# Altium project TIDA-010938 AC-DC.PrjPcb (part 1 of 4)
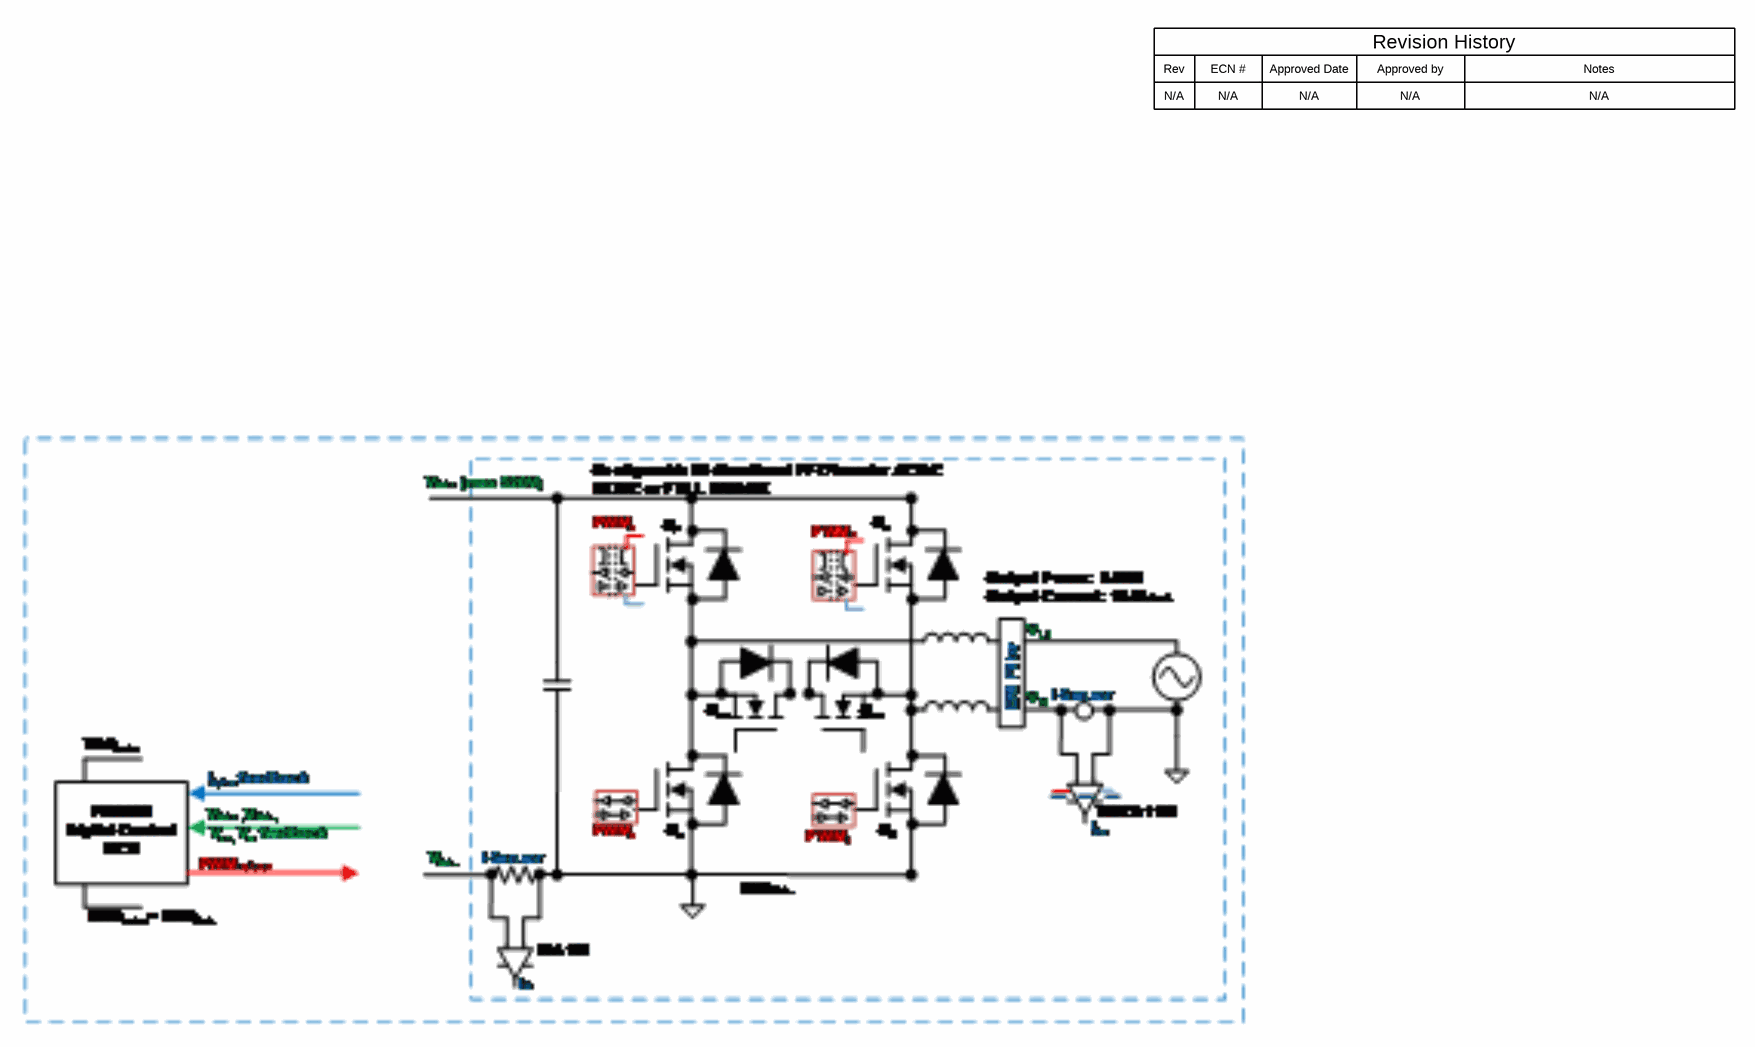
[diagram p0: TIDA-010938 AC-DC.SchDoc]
CopyrightYear: 2023; PCB_Layout: Vedatroyee Ghosh; PCB_Rev: E1; PRJ_Customer: Public Release; PRJ_Engineer: Vedatroyee Ghosh; PRJ_Number: TIDA-010938 AC-DC; PRJ_Title: TIDA-010938 AC-DC; SCH_Rev: E1; TechSupport: http://www.ti.com/support; TID: A0498176
11 sheets, 712 parts. Net scope: flat (ports and power ports of the same name join across sheets).
Board file: TIDA-010938 AC-DC.PcbDoc
Sheets:
  TIDA-010938 AC-DC.SchDoc
    Designator = TIDA-010938 AC-DC_Cover Sheet.SchDoc
      Designator = TIDA-010938 AC-DC_Power Stage_BranchA.SchDoc
      Designator = TIDA-010938 AC-DC_Power Stage_BranchB.SchDoc
      Designator = TIDA-010938 AC-DC_EMI Protection Stage.SchDoc
      Designator = TIDA-010938 AC-DC_Voltage Measurement.SchDoc
      Designator = TIDA-010938 AC-DC_Control Stage.SchDoc
        Designator = TIDA-010938 AC-DC_Communication.SchDoc
        Designator = TIDA-010938 AC-DC_OpAmp.SchDoc
      Designator = TIDA-010938 AC-DC_Hardware.SchDoc
      Designator = TIDA-010938 AC-DC_Aux Power Supply.SchDoc

## Sheet TIDA-010938 AC-DC.SchDoc
size 431 x 279 mm; Date: Not shown in title block; ApprovedBy: Not shown in title block; CheckedBy: Not shown in title block; Author: Not shown in title block; CompanyName: Not shown in title block; Engineer: Not shown in title block; Organization: Not shown in title block; Address1: Not shown in title block; Address2: Not shown in title block; Address3: Not shown in title block; Address4: Not shown in title block; DocumentNumber: 1; Revision: Use project parameter SCH_Rev; SheetNumber: 1; SheetTotal: 11; PageSetup: Record=PageOptions¦CenterHorizontal=True¦CenterVertical=True¦PrintScale=1.00¦XCorrection=1.00¦YCorrection=1.00¦PrintKind=0¦BorderSize=5000000¦LeftOffset=0¦BottomOffset=0¦Orientation=2¦PaperLength=1000¦PaperWidth=1000¦Scale=100¦PaperSource=15¦PrintQuality=600¦MediaType=1¦DitherType=10¦PaperKind=Letter¦PrintScaleMode=1

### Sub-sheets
Designator = TIDA-010938 AC-DC_Cover Sheet: no entries

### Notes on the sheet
- Rev
- N/A
- ECN #
- Approved Date
- Approved by
- Revision History
- Notes

## Sheet TIDA-010938 AC-DC_Cover Sheet.SchDoc
size 431 x 279 mm; Date: Not shown in title block; ApprovedBy: Not shown in title block; CheckedBy: Not shown in title block; Author: Not shown in title block; CompanyName: Not shown in title block; Engineer: Not shown in title block; Organization: Not shown in title block; Address1: Not shown in title block; Address2: Not shown in title block; Address3: Not shown in title block; Address4: Not shown in title block; DocumentNumber: 8; Revision: Use project parameter SCH_Rev; SheetNumber: 2; SheetTotal: 11; PageSetup: Record=PageOptions¦CenterHorizontal=True¦CenterVertical=True¦PrintScale=1.00¦XCorrection=1.00¦YCorrection=1.00¦PrintKind=0¦BorderSize=5000000¦LeftOffset=0¦BottomOffset=0¦Orientation=2¦PaperLength=1000¦PaperWidth=1000¦Scale=100¦PaperSource=15¦PrintQuality=600¦MediaType=1¦DitherType=10¦PaperKind=Letter¦PrintScaleMode=1
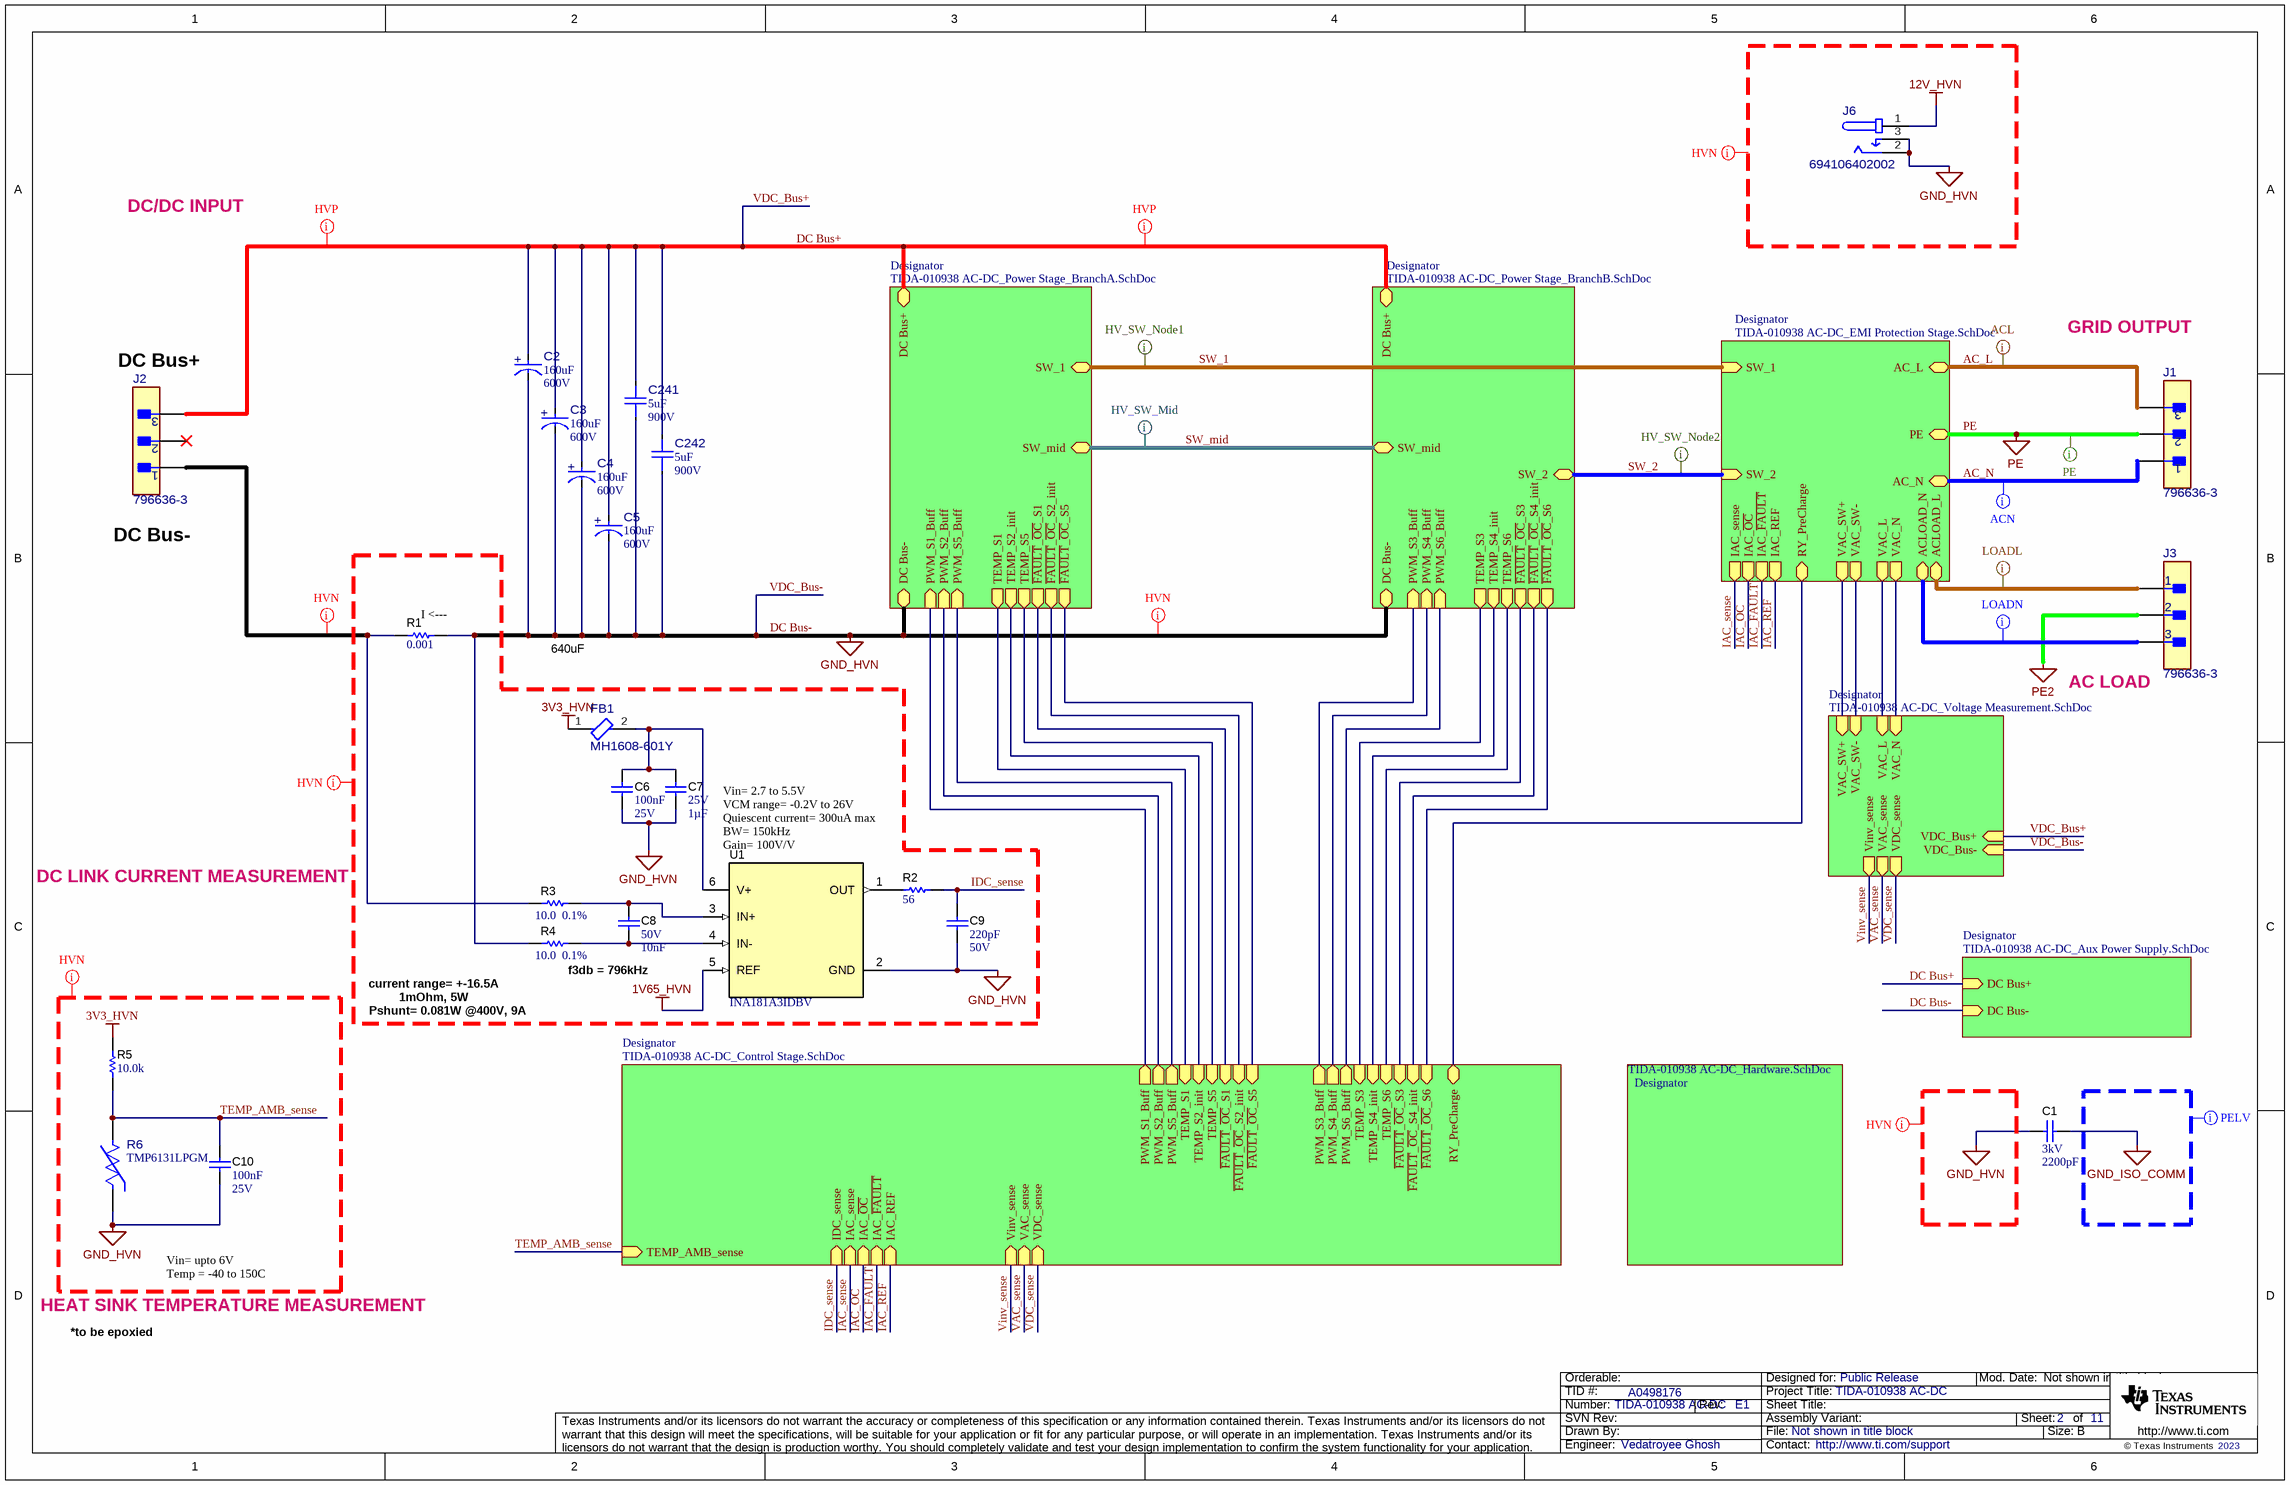
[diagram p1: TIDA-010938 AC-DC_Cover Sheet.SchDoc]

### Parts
C1  VDC_V: 3kV  ValueDisplayed: 2200pF  [CK45_1250x600x1650]  (hidden comment: CK45-B3FD222KYVNA)
C2  ValueDisplayed: 160uF  VDC_V: 600V  [FP-ALH82D161DD600_RADIAL-MFG]  (hidden comment: ALH82D161DD600)
C3  ValueDisplayed: 160uF  VDC_V: 600V  [FP-ALH82D161DD600_RADIAL-MFG]  (hidden comment: ALH82D161DD600)
C4  ValueDisplayed: 160uF  VDC_V: 600V  [FP-ALH82D161DD600_RADIAL-MFG]  (hidden comment: ALH82D161DD600)
C5  ValueDisplayed: 160uF  VDC_V: 600V  [FP-ALH82D161DD600_RADIAL-MFG]  (hidden comment: ALH82D161DD600)
C6  Cap_F: 100nF  VDC_V: 25V  [0603]  (hidden comment: 06033C104JAT2A)
C7  VDC_V: 25V  ValueDisplayed: 1µF  [0603]  (hidden comment: TMK107BJ105KA-T)
C8  VDC_V: 50V  Cap_F: 10nF  [0603]  (hidden comment: 885012206089)
C9  Cap_F: 220pF  VDC_V: 50V  [0603]  (hidden comment: GRM188R71H221KA01D)
C10  Cap_F: 100nF  VDC_V: 25V  [0603]  (hidden comment: 06033C104JAT2A)
C241  ValueDisplayed: 5uF  VDC_V: 900V  [FP-C4AKOBU4500A31J_RADIAL-MFG]  (hidden comment: C4AKOBU4500A31J)
C242  ValueDisplayed: 5uF  VDC_V: 900V  [FP-C4AKOBU4500A31J_RADIAL-MFG]  (hidden comment: C4AKOBU4500A31J)
FB1  MH1608-601Y  [FP-MH1608-601Y_0603-MFG]
J1  796636-3  [FP-796636-3_HDR3-MFG]
J2  796636-3  [FP-796636-3_HDR3-MFG]
J3  796636-3  [FP-796636-3_HDR3-MFG]
J6  694106402002  [FP-694106402002_CONN_PWR_10MM7_9MM0-MFG]
R1  ValueDisplayed: 0.001  [CSS2H-2512_H077Y042]  (hidden comment: CSS2H-2512R-1L00F)
R2  ValueDisplayed: 56  [0603]  (hidden comment: RG1608P-560-B-T5)
R3  Tolerance_%: 0.1%  ValueDisplayed: 10.0  [0603]  (hidden comment: RT0603BRD0710RL)
R4  Tolerance_%: 0.1%  ValueDisplayed: 10.0  [0603]  (hidden comment: RT0603BRD0710RL)
R5  ValueDisplayed: 10.0k  [0603]  (hidden comment: RG1608P-103-B-T5)
R6  TMP6131LPGM  [LPG0002A-MFG]
U1  INA181A3IDBV  [DBV0006A_N]

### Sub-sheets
Designator = TIDA-010938 AC-DC_Power Stage_BranchA.SchDoc: TEMP_S5 (out), TEMP_S1 (out), DC Bus+ (bidir), SW_mid (bidir), SW_1 (bidir), DC Bus- (bidir), PWM_S1_Buff (in), PWM_S5_Buff (in), PWM_S2_Buff (in), TEMP_S2_init (out), ~{FAULT}_~{OC}_S5 (out), ~{FAULT}_~{OC}_S1 (out), ~{FAULT}_~{OC}_S2_init (out)
Designator = TIDA-010938 AC-DC_Power Stage_BranchB.SchDoc: TEMP_S6 (out), TEMP_S3 (out), DC Bus+ (bidir), SW_mid (bidir), SW_2 (bidir), DC Bus- (bidir), PWM_S6_Buff (in), PWM_S3_Buff (in), PWM_S4_Buff (in), TEMP_S4_init (out), ~{FAULT}_~{OC}_S6 (out), ~{FAULT}_~{OC}_S3 (out), ~{FAULT}_~{OC}_S4_init (out)
Designator = TIDA-010938 AC-DC_EMI Protection Stage.SchDoc: AC_L (bidir), AC_N (bidir), SW_1 (in), SW_2 (in), VAC_SW+ (out), VAC_SW- (out), VAC_L (out), VAC_N (out), IAC_sense (out), IAC_~{OC} (out), IAC_~{FAULT} (out), IAC_REF (out), RY_PreCharge (bidir), PE (bidir), ACLOAD_L (bidir), ACLOAD_N (bidir)
Designator = TIDA-010938 AC-DC_Voltage Measurement.SchDoc: VDC_sense (out), Vinv_sense (out), VAC_N (in), VAC_L (in), VAC_SW- (in), VAC_SW+ (in), VAC_sense (out), VDC_Bus+ (in), VDC_Bus- (in)
Designator = TIDA-010938 AC-DC_Control Stage.SchDoc: IAC_REF (in), IAC_sense (in), VAC_sense (in), Vinv_sense (in), VDC_sense (in), IDC_sense (in), TEMP_AMB_sense (in), PWM_S1_Buff (out), PWM_S2_Buff (out), PWM_S3_Buff (out), PWM_S4_Buff (out), PWM_S5_Buff (out), PWM_S6_Buff (out), TEMP_S2_init (in), TEMP_S4_init (in), RY_PreCharge (bidir), IAC_~{FAULT} (in), IAC_~{OC} (in), TEMP_S1 (in), TEMP_S3 (in), TEMP_S5 (in), TEMP_S6 (in), ~{FAULT}_~{OC}_S5 (in), ~{FAULT}_~{OC}_S6 (in), ~{FAULT}_~{OC}_S1 (in), ~{FAULT}_~{OC}_S3 (in), ~{FAULT}_~{OC}_S2_init (in), ~{FAULT}_~{OC}_S4_init (in)
Designator = TIDA-010938 AC-DC_Hardware.SchDoc: no entries
Designator = TIDA-010938 AC-DC_Aux Power Supply.SchDoc: DC Bus+ (in), DC Bus- (in)

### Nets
1V65_HVN: U1.5(REF)
3V3_HVN: FB1.1 R5.2
12V_HVN: J6.1
DC Bus-: C1.2 C2.1(CATHODE) C3.1(CATHODE) C4.1(CATHODE) C5.1(CATHODE) C6.2 C7.2 C9.1 C10.2 C241.1 C242.1 J6.2 J6.3 R1.2 R4.1 R6.2(+) U1.2(GND) ; sheet Designator/DC Bus-, sheet Designator/DC Bus-, sheet Designator/VDC_Bus-, sheet Designator/DC Bus-  [also labelled GND_HVN, VDC_Bus-]
GND_ISO_COMM: C1.1
PE: J1.2 ; sheet Designator/PE
PE2: J3.2
AC_L: J1.3 ; sheet Designator/AC_L
AC_N: J1.1 ; sheet Designator/AC_N
DC Bus+: C2.2(ANODE) C3.2(ANODE) C4.2(ANODE) C5.2(ANODE) C241.2 C242.2 J2.3 ; sheet Designator/DC Bus+, sheet Designator/DC Bus+, sheet Designator/VDC_Bus+, sheet Designator/DC Bus+  [also labelled VDC_Bus+]
IAC_~{FAULT}: sheet Designator/IAC_~{FAULT}, sheet Designator/IAC_~{FAULT}
IAC_~{OC}: sheet Designator/IAC_~{OC}, sheet Designator/IAC_~{OC}
IAC_REF: sheet Designator/IAC_REF, sheet Designator/IAC_REF
IAC_sense: sheet Designator/IAC_sense, sheet Designator/IAC_sense
IDC_sense: C9.2 R2.2 ; sheet Designator/IDC_sense
SW_1: sheet Designator/SW_1, sheet Designator/SW_1
SW_2: sheet Designator/SW_2, sheet Designator/SW_2
SW_mid: sheet Designator/SW_mid, sheet Designator/SW_mid
TEMP_AMB_sense: C10.1 R5.1 R6.1(-) ; sheet Designator/TEMP_AMB_sense
VAC_sense: sheet Designator/VAC_sense, sheet Designator/VAC_sense
VDC_sense: sheet Designator/VDC_sense, sheet Designator/VDC_sense
Vinv_sense: sheet Designator/Vinv_sense, sheet Designator/Vinv_sense
NetC6_1: C6.1 C7.1 FB1.2 U1.6(V+)
NetC8_1: C8.1 R3.2 U1.3(IN+)
NetC8_2: C8.2 R4.2 U1.4(IN-)
NetJ2_1: J2.1 R1.1 R3.1
NetJ3_1: J3.1 ; sheet Designator/ACLOAD_L
NetJ3_3: J3.3 ; sheet Designator/ACLOAD_N
NetR2_1: R2.1 U1.1(OUT)
(unnamed): sheet Designator/TEMP_S5, sheet Designator/TEMP_S5
(unnamed): sheet Designator/TEMP_S1, sheet Designator/TEMP_S1  [a separate net that carries the same name]
(unnamed): sheet Designator/PWM_S1_Buff, sheet Designator/PWM_S1_Buff  [a separate net that carries the same name]
(unnamed): sheet Designator/PWM_S5_Buff, sheet Designator/PWM_S5_Buff  [a separate net that carries the same name]
(unnamed): sheet Designator/PWM_S2_Buff, sheet Designator/PWM_S2_Buff  [a separate net that carries the same name]
(unnamed): sheet Designator/TEMP_S2_init, sheet Designator/TEMP_S2_init  [a separate net that carries the same name]
(unnamed): sheet Designator/~{FAULT}_~{OC}_S5, sheet Designator/~{FAULT}_~{OC}_S5  [a separate net that carries the same name]
(unnamed): sheet Designator/~{FAULT}_~{OC}_S1, sheet Designator/~{FAULT}_~{OC}_S1  [a separate net that carries the same name]
(unnamed): sheet Designator/~{FAULT}_~{OC}_S2_init, sheet Designator/~{FAULT}_~{OC}_S2_init  [a separate net that carries the same name]
(unnamed): sheet Designator/TEMP_S6, sheet Designator/TEMP_S6  [a separate net that carries the same name]
(unnamed): sheet Designator/TEMP_S3, sheet Designator/TEMP_S3  [a separate net that carries the same name]
(unnamed): sheet Designator/PWM_S6_Buff, sheet Designator/PWM_S6_Buff  [a separate net that carries the same name]
(unnamed): sheet Designator/PWM_S3_Buff, sheet Designator/PWM_S3_Buff  [a separate net that carries the same name]
(unnamed): sheet Designator/PWM_S4_Buff, sheet Designator/PWM_S4_Buff  [a separate net that carries the same name]
(unnamed): sheet Designator/TEMP_S4_init, sheet Designator/TEMP_S4_init  [a separate net that carries the same name]
(unnamed): sheet Designator/~{FAULT}_~{OC}_S6, sheet Designator/~{FAULT}_~{OC}_S6  [a separate net that carries the same name]
(unnamed): sheet Designator/~{FAULT}_~{OC}_S3, sheet Designator/~{FAULT}_~{OC}_S3  [a separate net that carries the same name]
(unnamed): sheet Designator/~{FAULT}_~{OC}_S4_init, sheet Designator/~{FAULT}_~{OC}_S4_init  [a separate net that carries the same name]
(unnamed): sheet Designator/VAC_SW+, sheet Designator/VAC_SW+  [a separate net that carries the same name]
(unnamed): sheet Designator/VAC_SW-, sheet Designator/VAC_SW-  [a separate net that carries the same name]
(unnamed): sheet Designator/VAC_L, sheet Designator/VAC_L  [a separate net that carries the same name]
(unnamed): sheet Designator/VAC_N, sheet Designator/VAC_N  [a separate net that carries the same name]
(unnamed): sheet Designator/RY_PreCharge, sheet Designator/RY_PreCharge  [a separate net that carries the same name]

Not connected (* = marked no-connect by the designer): J2 2*

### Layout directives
net class HVN: 1V65_HVN, 3V3_HVN, 12V_HVN, DC Bus-, GND_HVN, IDC_sense, NetJ2_1, TEMP_AMB_sense, VDC_Bus-
net class HVP: DC Bus+
net class PELV: GND_ISO_COMM
net class ACL: AC_L
net class ACN: AC_N
net class PE: PE
net class HV_SW_Node1: SW_1
net class HV_SW_Mid: SW_mid
net class HV_SW_Node2: SW_2
net class LOADL: NetJ3_1
net class LOADN: NetJ3_3

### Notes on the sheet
- DC/DC INPUT
- (near J2) DC Bus+
- GRID OUTPUT
- DC Bus-
- (near R1) I <---
- 640uF
- (near J3) AC LOAD
- DC LINK CURRENT MEASUREMENT
- Vin= 2.7 to 5.5V
  VCM range= -0.2V to 26V
  Quiescent current= 300uA max
  BW= 150kHz
  Gain= 100V/V
- f3db = 796kHz
- (near R4) current range= +-16.5A
- 1mOhm, 5W
- Pshunt= 0.081W @400V, 9A
- Vin= upto 6V
  Temp = -40 to 150C
- HEAT SINK TEMPERATURE MEASUREMENT
- *to be epoxied

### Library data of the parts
C1 = CMP-0086078-1: CAP, CERM, 2200 pF, 3000 V,+/- 10%, B, Dia 12.5mm; Manufacturer: TDK; AEC Qualified: N; SizeAreaWB_mm2: 116; Cap_Case: 12.5x6x16.5mm; SizeZ_mm: 16.5; AEC Category: Q200; TaMin_C: -25°C; SizeX_mm: 12.5; SizeY_mm: 6; Value2: 3000V; TaMax_C: 105°C; Value: 2200pF; SizeArea_mm2: 75; U/M: EA; Cap_F: 2.2nF
C2-C5 = CMP-0033686-1: ALH82, Aluminum Electrolytic, 160 uF, 20%, 600 VDC, -40/+105°C; Manufacturer: KEMET; AEC Qualified: No; Cap_F: 160µF; IRMS_A: 4.51A; SizeZ_mm: 42mm; Esr: 0.877; Leakage Current: 288uA; Life: 3000Hours; Value: 160µF
C6 C10 = CMP-0006752-5: CAP, CERM, 0.1 uF, 25 V, +/- 5%, X7R, 0603; Manufacturer: AVX; TaMin_C: -55°C; ESR_ohm: 0.05; Polarized: N; SizeAreaWB_mm2: 4.68; Value1: 0.05 ohm; U/M: EA; Value: 0.1uF; TaMax_C: 125°C; SizeZ_mm: 1; SizeX_mm: 1.6; SizeY_mm: 0.8; SizeArea_mm2: 1.28; AEC Category: Q200
C7 = CMP-0086152-1: CAP, CERM, 1 µF, 25 V,+/- 10%, X5R, 0603; Manufacturer: Taiyo Yuden; SizeAreaWB_mm2: 4.68; SizeZ_mm: 1; U/M: EA; Green_REACh: Passed; Value: 1uF; AEC Qualified: N; TaMax_C: 85°C; Green_Lifecycle: Active; AEC Category: Q200; SizeArea_mm2: 1.28; TaMin_C: -55°C; SizeY_mm: 0.8; SizeX_mm: 1.6
C8 = CMP-0750039-1: CAP, CERM, 0.01 µF, 50 V,+/- 10%, X7R, 0603; Manufacturer: Wurth Elektronik; Polarized: N; AEC Category: Q200; TaMax_C: 125°C; SizeAreaWB_mm2: 4.68; Value: 0.01uF; SizeArea_mm2: 1.28; SizeY_mm: 0.8; SizeZ_mm: 1; ValueDisplayed: 0.01µF; SizeX_mm: 1.6; U/M: EA; TaMin_C: -55°C
C9 = CMP-0007442-5: CAP, CERM, 220 pF, 50 V, +/- 10%, X7R, 0603; Manufacturer: MuRata; TaMin_C: -55°C; Polarized: N; SizeAreaWB_mm2: 4.68; Value1: Unknown; U/M: EA; Value: 220pF; TaMax_C: 125°C; SizeZ_mm: 1; SizeX_mm: 1.6; SizeY_mm: 0.8; SizeArea_mm2: 1.28; AEC Category: Q200
C241 C242 = CMP-0037193-1: 5 µF Film Capacitor 900V Polypropylene (PP), Metallized Radial; Manufacturer: Kemet; AEC Grade: Grade 1; AEC Qualified: No; Cap_F: 5µF; SizeZ_mm: 29.7mm; Tolerance_%: 5%; Standoff Height: 0.5mm; Value: 5µF
FB1 = CMP-0037505-1: 600 Ohms @ 100 MHz 1 Power, Signal Line Ferrite Bead 0603 (1608 Metric) 1A 200mOhm; Manufacturer: Bourns; DCR_ohm: 0.2; SizeZ_mm: 1mm; AEC Qualified: No; Impedance At Frequency: 600Ω @ 100MHz; Test Frequency: 100MHz; Tolerance_%: 25%
J1-J3 = CMP-0094328-1: 3 Position Terminal Block Header, Male Pins, Shrouded (4 Side) 0.200" (5.08mm) Vertical - Through Hole; Manufacturer: TE Connectivity; Current_A: 15A; Row_Count: 1; AEC Qualified: No; Voltage_V: 300V; SizeZ_mm: 12.25mm; Min Wire Gauge: 30; ContactFinish: Tin; Max Wire Gauge: 12
J6 = CMP-0040211-1: Power Barrel Connector Jack 2.10mm ID (0.083"), 5.50mm OD (0.217") Through Hole; Manufacturer: Wurth Electronics; ContactFinish: Gold; Current_A: 3A; Voltage_V: 30V; AEC Qualified: No; Conn Gender: Female; Conn Orientation: Vertical; SizeZ_mm: 14.3mm
R1 = CMP-0084746-1: RES, 0.001, 1%, 5 W, AEC-Q200 Grade 0, 6.35x3.05mm; Manufacturer: Bourns; SizeAreaWB_mm2: 42.1675; SizeArea_mm2: 19.3675; SizeY_mm: 3.05; SizeX_mm: 6.35; AEC Grade: 0; EIA_Code: E96; Value: 0.001; Res_ohm: 1m; Power_W: 5W; SizeZ_mm: 0.87; TempCo: 75 ppm/C; Value_Code: 1L000; AEC Qualified: Y; AEC Category: Q200
R2 = CMP-0023572-3: RES, 56, 0.1%, 0.1 W, 0603; Manufacturer: Susumu Co Ltd; Power_W: 100mW; TempCo: 25 ppm/C; Value_Code: 56R0; U/M: EA; Value: 56; SizeX_mm: 1.6; SizeY_mm: 0.8; SizeZ_mm: 1; Value2: 0.1W; SizeArea_mm2: 1.28; VDC_V: 75V; AEC Category: Q200
R3 R4 = CMP-0023661-3: RES, 10.0, 0.1%, 0.1 W, 0603; Manufacturer: Yageo America; Power_W: 100mW; TempCo: 25 ppm/C; Value_Code: 10R0; U/M: EA; Value: 10.0; EIA_Code: E192; Res_ohm: 10; SizeX_mm: 1.6; SizeY_mm: 0.8; SizeZ_mm: 1; Value2: 0.1W; SizeArea_mm2: 1.28; VDC_V: 75V; AEC Category: Q200
R5 = CMP-0023404-3: RES, 10.0 k, 0.1%, 0.1 W, 0603; Manufacturer: Susumu Co Ltd; Power_W: 100mW; TempCo: 25 ppm/C; Value_Code: 10k0; U/M: EA; Value: 10.0k; EIA_Code: E192; Res_ohm: 10k; SizeX_mm: 1.6; SizeY_mm: 0.8; SizeZ_mm: 1; Value2: 0.1W; SizeArea_mm2: 1.28; VDC_V: 75V; AEC Category: Q200
R6 = CMP-0089579-1: SENSOR PTC 10K OHM 1% TO92S; Manufacturer: Texas Instruments; TJmax_C: +155°C; AEC Qualified: No; Value: 10kΩ; SizeZ_mm: 5.05mm; Max Current: 400uA; TaMax_C: +150°C; TempCo: 6400ppm/°C; TaMin_C: -40°C; VDC_V: 5.5V
U1 = CMP-0013234-2: Bidirectional, Low- and High-Side Measurement, Multichannel, Voltage Output, Current-Sense Amplifier, DBV0006A (SOT-6); Manufacturer: Texas Instruments; SizeX_mm: 2.8; SizeY_mm: 2.9; CompType: IC; SizeZ_mm: 1.45; SizeArea_mm2: 8.12; SizeAreaWB_mm2: 14.82; U/M: EA

## Sheet TIDA-010938 AC-DC_Power Stage_BranchA.SchDoc
size 558 x 431 mm; Date: Not shown in title block; ApprovedBy: Not shown in title block; CheckedBy: Not shown in title block; Author: Not shown in title block; CompanyName: Not shown in title block; Engineer: Not shown in title block; Organization: Not shown in title block; Address1: Not shown in title block; Address2: Not shown in title block; Address3: Not shown in title block; Address4: Not shown in title block; DocumentNumber: 2; Revision: Use project parameter SCH_Rev; SheetNumber: 3; SheetTotal: 11; PageSetup: Record=PageOptions¦CenterHorizontal=True¦CenterVertical=True¦PrintScale=1.00¦XCorrection=1.00¦YCorrection=1.00¦PrintKind=0¦BorderSize=5000000¦LeftOffset=0¦BottomOffset=0¦Orientation=2¦PaperLength=1000¦PaperWidth=1000¦Scale=100¦PaperSource=15¦PrintQuality=600¦MediaType=1¦DitherType=10¦PaperKind=Letter¦PrintScaleMode=1
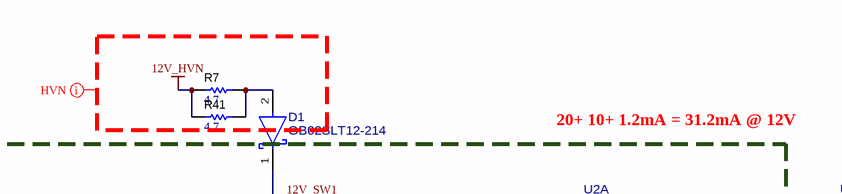
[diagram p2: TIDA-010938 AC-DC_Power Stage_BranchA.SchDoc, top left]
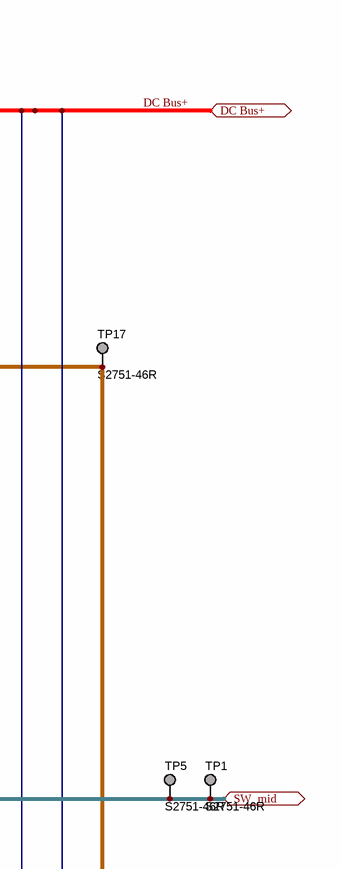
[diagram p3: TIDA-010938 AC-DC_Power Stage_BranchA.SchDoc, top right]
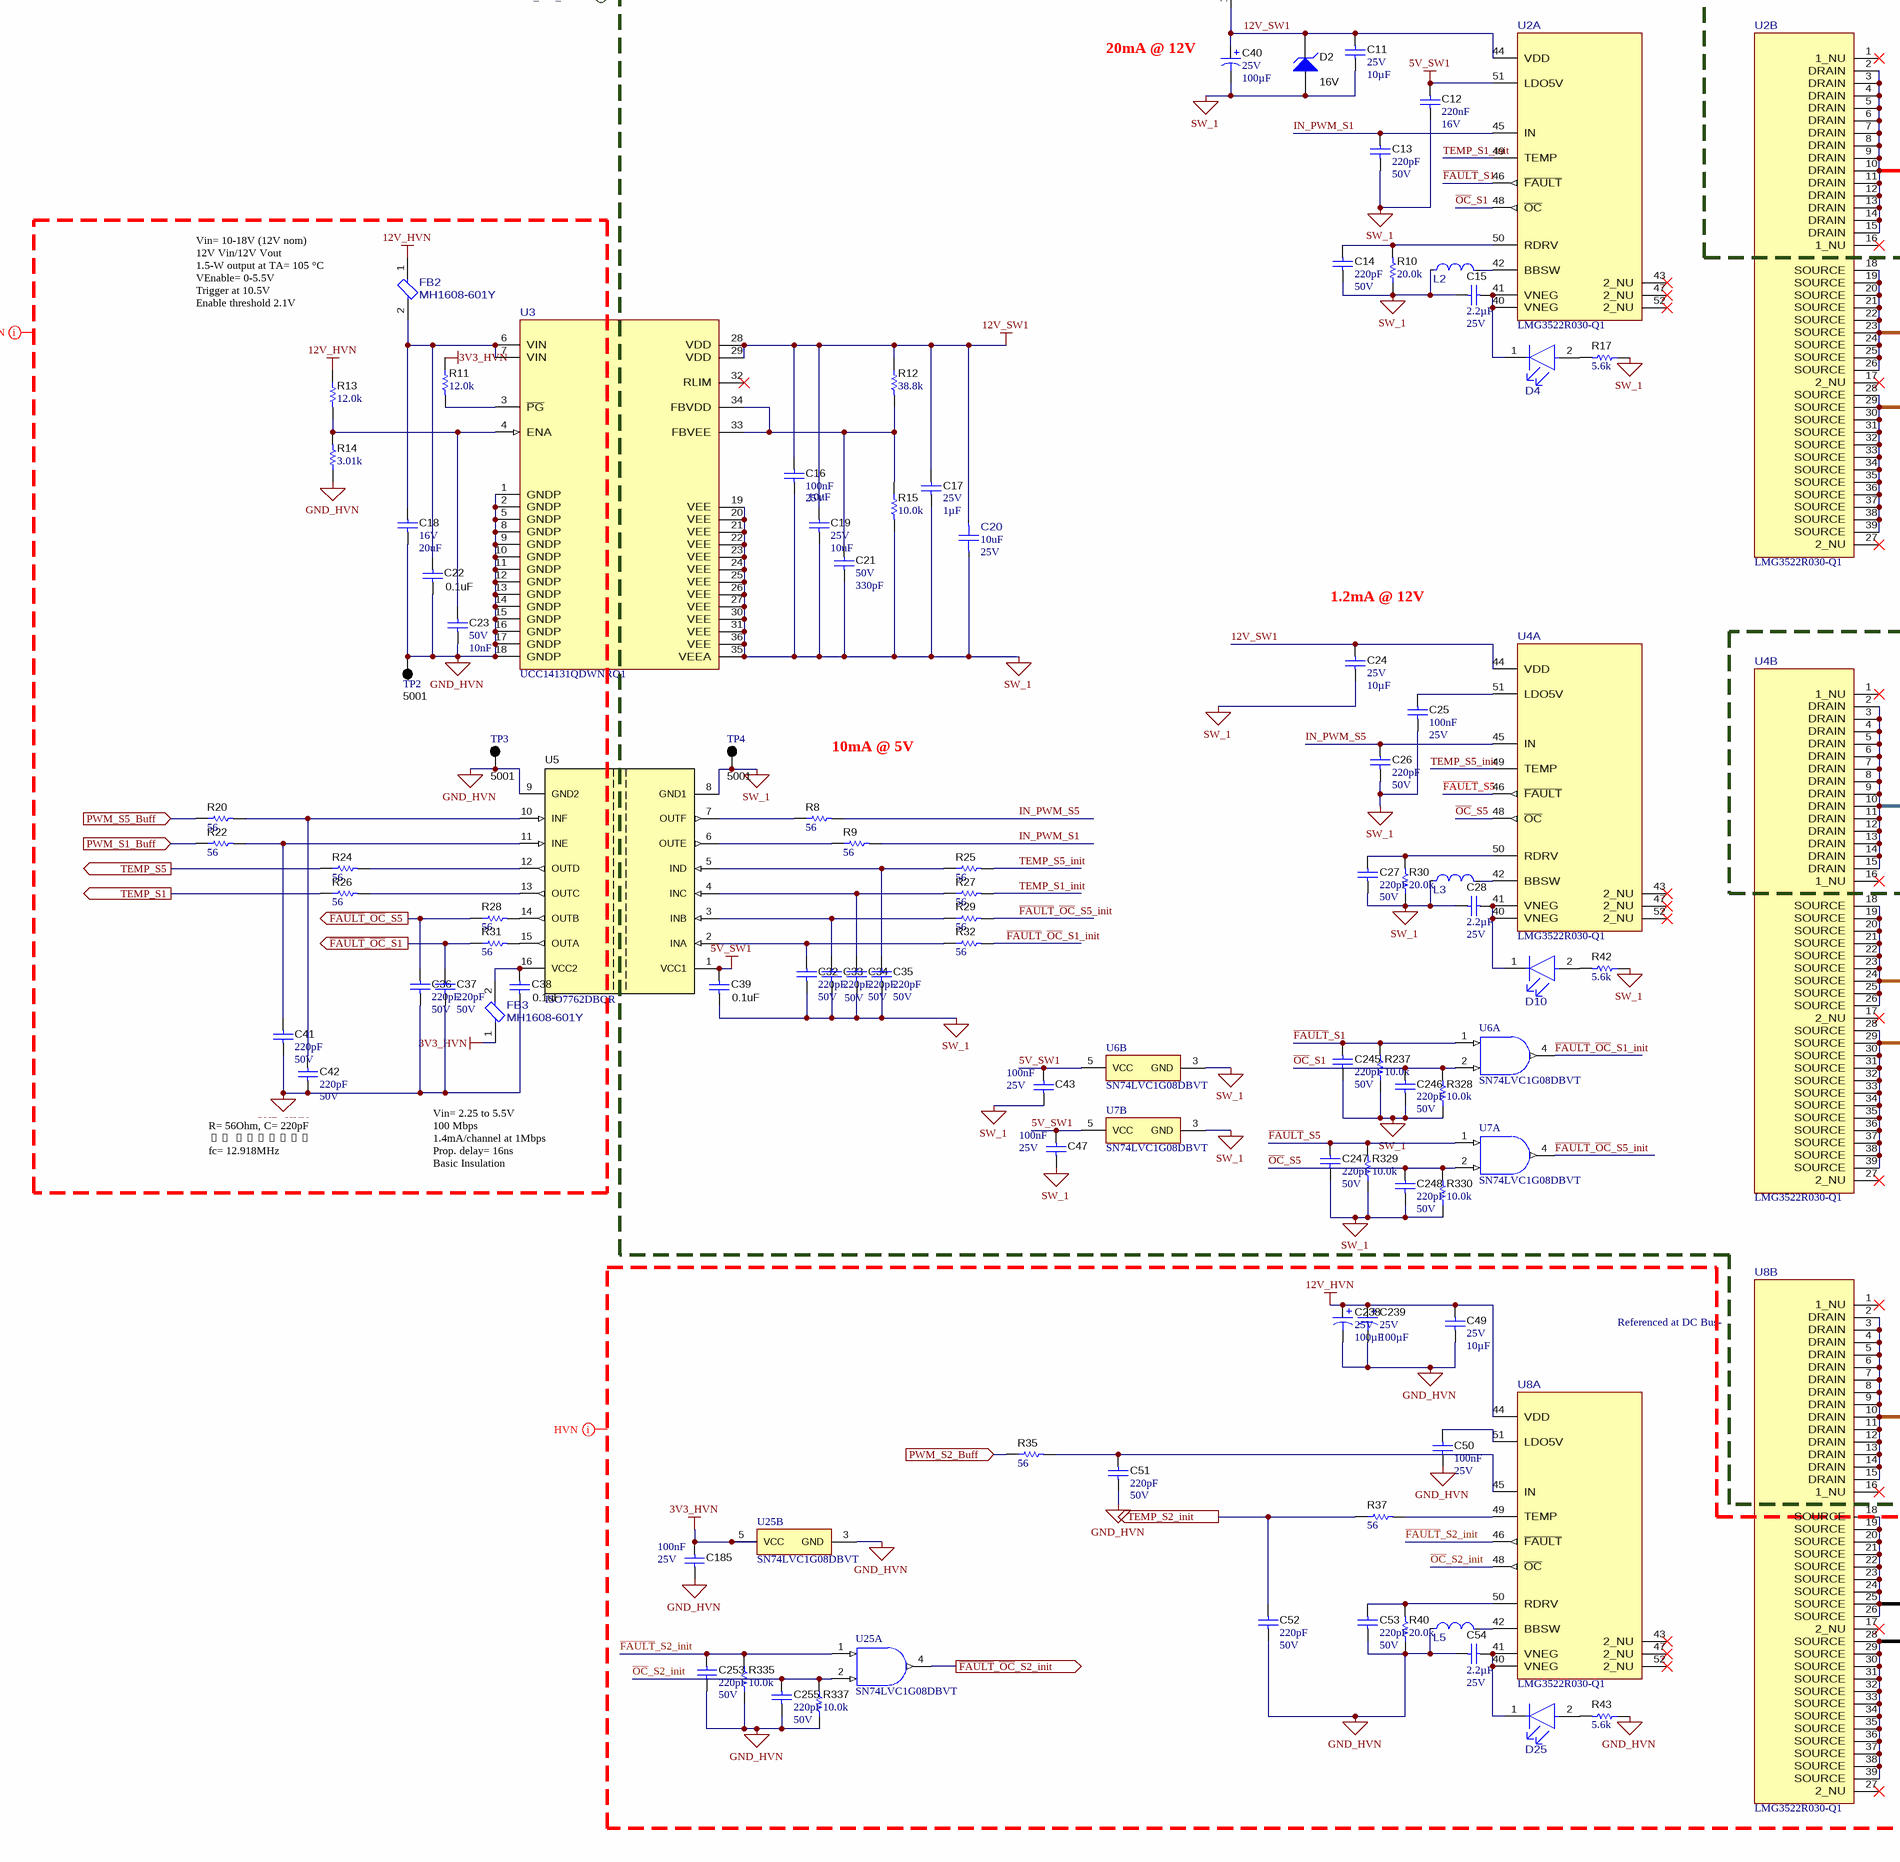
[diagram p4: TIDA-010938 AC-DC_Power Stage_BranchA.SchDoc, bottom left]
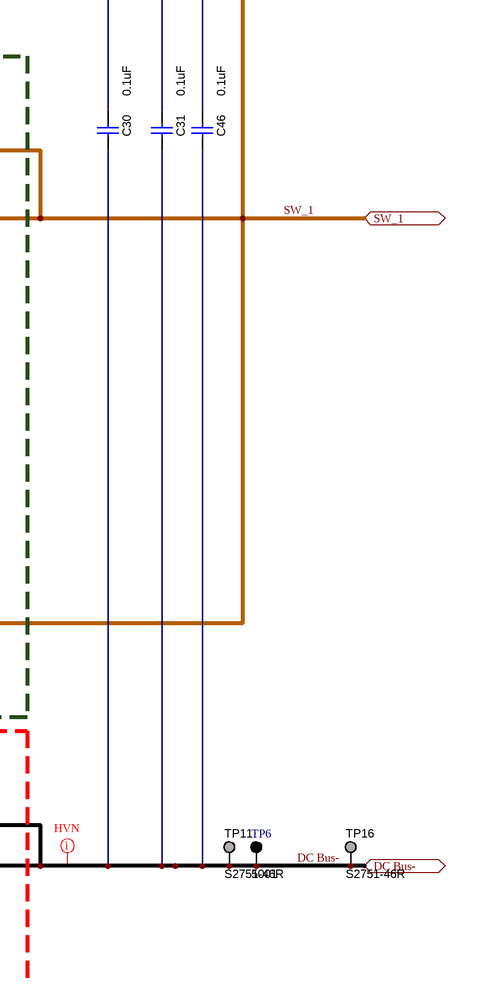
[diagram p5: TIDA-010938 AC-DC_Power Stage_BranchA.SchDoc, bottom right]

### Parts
C11  VDC_V: 25V  ValueDisplayed: 10µF  [1206_180]  (hidden comment: TMK316AB7106KLHT)
C12  Cap_F: 220nF  VDC_V: 16V  [0603]  (hidden comment: GRM188R71C224KA01D)
C13  Cap_F: 220pF  VDC_V: 50V  [0603]  (hidden comment: GRM188R71H221KA01D)
C14  Cap_F: 220pF  VDC_V: 50V  [0603]  (hidden comment: GRM188R71H221KA01D)
C15  Cap_F: 2.2µF  VDC_V: 25V  [0805_HV]  (hidden comment: CGA4J3X7R1E225K125AB)
C16  Cap_F: 100nF  VDC_V: 25V  [0603]  (hidden comment: 06033C104JAT2A)
C17  VDC_V: 25V  ValueDisplayed: 1µF  [0603]  (hidden comment: TMK107BJ105KA-T)
C18  VDC_V: 16V  ValueDisplayed: 20uF  [0704]  (hidden comment: GRMJN7R61C206ME05)
C19  value 10uF  VDC_V: 25V  [0603]  (hidden comment: TMK107BBJ106MA-T)
C20  ValueDisplayed: 10uF  VDC_V: 25V  [FP-ZRB18AR61E106ME01L_0603-MFG]  (hidden comment: ZRB18AR61E106ME01L)
C21  VDC_V: 50V  ValueDisplayed: 330pF  [0603]  (hidden comment: GRM1885C1H331JA01D)
C22  ValueDisplayed: 0.1uF  [0603]  (hidden comment: 885012206095)
C23  VDC_V: 50V  Cap_F: 10nF  [0603]  (hidden comment: 885012206089)
C24  VDC_V: 25V  ValueDisplayed: 10µF  [1206_180]  (hidden comment: TMK316AB7106KLHT)
C25  Cap_F: 100nF  VDC_V: 25V  [0603]  (hidden comment: 06033C104JAT2A)
C26  Cap_F: 220pF  VDC_V: 50V  [0603]  (hidden comment: GRM188R71H221KA01D)
C27  Cap_F: 220pF  VDC_V: 50V  [0603]  (hidden comment: GRM188R71H221KA01D)
C28  Cap_F: 2.2µF  VDC_V: 25V  [0805_HV]  (hidden comment: CGA4J3X7R1E225K125AB)
C30  ValueDisplayed: 0.1uF  [1812_254]  (hidden comment: C1812W104KDRACTU)
C31  ValueDisplayed: 0.1uF  [1812_254]  (hidden comment: C1812W104KDRACTU)
C32  Cap_F: 220pF  VDC_V: 50V  [0603]  (hidden comment: GRM188R71H221KA01D)
C33  Cap_F: 220pF  VDC_V: 50V  [0603]  (hidden comment: GRM188R71H221KA01D)
C34  Cap_F: 220pF  VDC_V: 50V  [0603]  (hidden comment: GRM188R71H221KA01D)
C35  Cap_F: 220pF  VDC_V: 50V  [0603]  (hidden comment: GRM188R71H221KA01D)
C36  Cap_F: 220pF  VDC_V: 50V  [0603]  (hidden comment: GRM188R71H221KA01D)
C37  Cap_F: 220pF  VDC_V: 50V  [0603]  (hidden comment: GRM188R71H221KA01D)
C38  ValueDisplayed: 0.1uF  [0603]  (hidden comment: 885012206095)
C39  ValueDisplayed: 0.1uF  [0603]  (hidden comment: 885012206095)
C40  VDC_V: 25V  ValueDisplayed: 100µF  [UWT_630x770]  (hidden comment: UWT1E101MCL1GS)
C41  Cap_F: 220pF  VDC_V: 50V  [0603]  (hidden comment: GRM188R71H221KA01D)
C42  Cap_F: 220pF  VDC_V: 50V  [0603]  (hidden comment: GRM188R71H221KA01D)
C43  Cap_F: 100nF  VDC_V: 25V  [0603]  (hidden comment: 06033C104JAT2A)
C46  ValueDisplayed: 0.1uF  [1812_254]  (hidden comment: C1812W104KDRACTU)
C47  Cap_F: 100nF  VDC_V: 25V  [0603]  (hidden comment: 06033C104JAT2A)
C49  VDC_V: 25V  ValueDisplayed: 10µF  [1206_180]  (hidden comment: TMK316AB7106KLHT)
C50  Cap_F: 100nF  VDC_V: 25V  [0603]  (hidden comment: 06033C104JAT2A)
C51  Cap_F: 220pF  VDC_V: 50V  [0603]  (hidden comment: GRM188R71H221KA01D)
C52  Cap_F: 220pF  VDC_V: 50V  [0603]  (hidden comment: GRM188R71H221KA01D)
C53  Cap_F: 220pF  VDC_V: 50V  [0603]  (hidden comment: GRM188R71H221KA01D)
C54  Cap_F: 2.2µF  VDC_V: 25V  [0805_HV]  (hidden comment: CGA4J3X7R1E225K125AB)
C185  Cap_F: 100nF  VDC_V: 25V  [0603]  (hidden comment: 06033C104JAT2A)
C238  VDC_V: 25V  ValueDisplayed: 100µF  [UWT_630x770]  (hidden comment: UWT1E101MCL1GS)
C239  VDC_V: 25V  ValueDisplayed: 100µF  [UWT_630x770]  (hidden comment: UWT1E101MCL1GS)
C245  Cap_F: 220pF  VDC_V: 50V  [0603]  (hidden comment: GRM188R71H221KA01D)
C246  Cap_F: 220pF  VDC_V: 50V  [0603]  (hidden comment: GRM188R71H221KA01D)
C247  Cap_F: 220pF  VDC_V: 50V  [0603]  (hidden comment: GRM188R71H221KA01D)
C248  Cap_F: 220pF  VDC_V: 50V  [0603]  (hidden comment: GRM188R71H221KA01D)
C253  Cap_F: 220pF  VDC_V: 50V  [0603]  (hidden comment: GRM188R71H221KA01D)
C255  Cap_F: 220pF  VDC_V: 50V  [0603]  (hidden comment: GRM188R71H221KA01D)
D1  GB02SLT12-214  [FP-GB02SLT12-214_DO-214AA-MFG]
D2  value 16V  [SOD-123]  (hidden comment: BZT52C16-7-F)
D4  KG DELLS1.22-JGKH-24  [FP-KG DELLS1.22-JGKH-24_0603-MFG]  (value not drawn)
D10  KG DELLS1.22-JGKH-24  [FP-KG DELLS1.22-JGKH-24_0603-MFG]  (value not drawn)
D25  KG DELLS1.22-JGKH-24  [FP-KG DELLS1.22-JGKH-24_0603-MFG]  (value not drawn)
FB2  MH1608-601Y  [FP-MH1608-601Y_0603-MFG]
FB3  MH1608-601Y  [FP-MH1608-601Y_0603-MFG]
L2  SDEM20161T-4R7MS  [FP-SDEM20161T-4R7MS_SMD2-MFG]  (value not drawn)
L3  SDEM20161T-4R7MS  [FP-SDEM20161T-4R7MS_SMD2-MFG]  (value not drawn)
L5  SDEM20161T-4R7MS  [FP-SDEM20161T-4R7MS_SMD2-MFG]  (value not drawn)
R7  ValueDisplayed: 4.7  [1206]  (hidden comment: CRCW12064R70JNEAHP)
R8  ValueDisplayed: 56  [0603]  (hidden comment: RG1608P-560-B-T5)
R9  ValueDisplayed: 56  [0603]  (hidden comment: RG1608P-560-B-T5)
R10  ValueDisplayed: 20.0k  [0603]  (hidden comment: RC0603FR-0720KL)
R11  ValueDisplayed: 12.0k  [0603]  (hidden comment: ERJ-3EKF1202V)
R12  ValueDisplayed: 38.8k  [0603]  (hidden comment: RT0603DRE0738K8L)
R13  ValueDisplayed: 12.0k  [0603]  (hidden comment: ERJ-3EKF1202V)
R14  ValueDisplayed: 3.01k  [0603]  (hidden comment: RC0603FR-073K01L)
R15  ValueDisplayed: 10.0k  [0603]  (hidden comment: RG1608P-103-B-T5)
R17  ValueDisplayed: 5.6k  [0603]  (hidden comment: RC0603JR-075K6L)
R20  ValueDisplayed: 56  [0603]  (hidden comment: RG1608P-560-B-T5)
R22  ValueDisplayed: 56  [0603]  (hidden comment: RG1608P-560-B-T5)
R24  ValueDisplayed: 56  [0603]  (hidden comment: RG1608P-560-B-T5)
R25  ValueDisplayed: 56  [0603]  (hidden comment: RG1608P-560-B-T5)
R26  ValueDisplayed: 56  [0603]  (hidden comment: RG1608P-560-B-T5)
R27  ValueDisplayed: 56  [0603]  (hidden comment: RG1608P-560-B-T5)
R28  ValueDisplayed: 56  [0603]  (hidden comment: RG1608P-560-B-T5)
R29  ValueDisplayed: 56  [0603]  (hidden comment: RG1608P-560-B-T5)
R30  ValueDisplayed: 20.0k  [0603]  (hidden comment: RC0603FR-0720KL)
R31  ValueDisplayed: 56  [0603]  (hidden comment: RG1608P-560-B-T5)
R32  ValueDisplayed: 56  [0603]  (hidden comment: RG1608P-560-B-T5)
R35  ValueDisplayed: 56  [0603]  (hidden comment: RG1608P-560-B-T5)
R37  ValueDisplayed: 56  [0603]  (hidden comment: RG1608P-560-B-T5)
R40  ValueDisplayed: 20.0k  [0603]  (hidden comment: RC0603FR-0720KL)
R41  ValueDisplayed: 4.7  [1206]  (hidden comment: CRCW12064R70JNEAHP)
R42  ValueDisplayed: 5.6k  [0603]  (hidden comment: RC0603JR-075K6L)
R43  ValueDisplayed: 5.6k  [0603]  (hidden comment: RC0603JR-075K6L)
R237  ValueDisplayed: 10.0k  [0603]  (hidden comment: RG1608P-103-B-T5)
R328  ValueDisplayed: 10.0k  [0603]  (hidden comment: RG1608P-103-B-T5)
R329  ValueDisplayed: 10.0k  [0603]  (hidden comment: RG1608P-103-B-T5)
R330  ValueDisplayed: 10.0k  [0603]  (hidden comment: RG1608P-103-B-T5)
R335  ValueDisplayed: 10.0k  [0603]  (hidden comment: RG1608P-103-B-T5)
R337  ValueDisplayed: 10.0k  [0603]  (hidden comment: RG1608P-103-B-T5)
TP1  S2751-46R  [Harwin_S2751-46R]  (no BOM)
TP2  5001  [Keystone5001]
TP3  5001  [Keystone5001]
TP4  5001  [Keystone5001]
TP5  S2751-46R  [Harwin_S2751-46R]  (no BOM)
TP6  5001  [Keystone5001]
TP11  S2751-46R  [Harwin_S2751-46R]  (no BOM)
TP16  S2751-46R  [Harwin_S2751-46R]  (no BOM)
TP17  S2751-46R  [Harwin_S2751-46R]  (no BOM)
U2  LMG3522R030-Q1  [RQS0052C-C01-MFG]  (parts A,B of 2)
U3  UCC14131QDWNRQ1  [DWJ0036A-MFG]
U4  LMG3522R030-Q1  [RQS0052C-C01-MFG]  (parts A,B of 2)
U5  ISO7762DBQR  [DBQ0016A_N]
U6  SN74LVC1G08DBVT  [DBV0005A_N]  (parts A,B of 2)
U7  SN74LVC1G08DBVT  [DBV0005A_N]  (parts A,B of 2)
U8  LMG3522R030-Q1  [RQS0052C-C01-MFG]  (parts A,B of 2)
U25  SN74LVC1G08DBVT  [DBV0005A_N]  (parts A,B of 2)

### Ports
DC Bus+ (bidir), DC Bus- (bidir), PWM_S1_Buff (in), PWM_S2_Buff (in), PWM_S5_Buff (in), SW_1 (bidir), SW_mid (bidir), TEMP_S1 (out), TEMP_S2_init (out), TEMP_S5 (out), ~{FAULT}_~{OC}_S1 (out), ~{FAULT}_~{OC}_S2_init (out), ~{FAULT}_~{OC}_S5 (out)

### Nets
3V3_HVN: C185.1 FB3.1 R11.1 U25.5(VCC)
5V_SW1: C12.1 C39.1 C43.1 C47.1 U2.51(LDO5V) U5.1(VCC1) U6.5(VCC) U7.5(VCC)
12V_HVN: C49.1 C238.1(+) C239.1(+) FB2.1 R7.1 R13.1 R41.1 U8.44(VDD)
12V_SW1: C11.1 C16.2 C17.2 C19.2 C20.1 C24.1 C40.1(+) D1.1(CATHODE) D2.1(K) R12.1 U2.44(VDD) U3.28(VDD) U3.29(VDD) U4.44(VDD)
DC Bus-: C18.1 C22.2 C23.1 C30.2 C31.2 C36.1 C37.1 C38.2 C41.1 C42.1 C46.2 C49.2 C50.1 C51.1 C52.1 C53.1 C54.2 C185.2 C238.2(-) C239.2(-) C253.1 C255.1 L5.1 R14.1 R40.1 R43.1 R335.1 R337.1 TP2.1 TP3.1 TP6.1 TP11.1 TP16.1 U3.1(GNDP) U3.2(GNDP) U3.5(GNDP) U3.8(GNDP) U3.9(GNDP) U3.10(GNDP) U3.11(GNDP) U3.12(GNDP) U3.13(GNDP) U3.14(GNDP) U3.15(GNDP) U3.16(GNDP) U3.17(GNDP) U3.18(GNDP) U5.9(GND2) U8.18(SOURCE) U8.19(SOURCE) U8.20(SOURCE) U8.21(SOURCE) U8.22(SOURCE) U8.23(SOURCE) U8.24(SOURCE) U8.25(SOURCE) U8.26(SOURCE) U8.28(SOURCE) U8.29(SOURCE) U8.30(SOURCE) U8.31(SOURCE) U8.32(SOURCE) U8.33(SOURCE) U8.34(SOURCE) U8.35(SOURCE) U8.36(SOURCE) U8.37(SOURCE) U8.38(SOURCE) U8.39(SOURCE) U25.3(GND) ; port DC Bus-  [also labelled GND_HVN]
SW_1: C11.2 C12.2 C13.1 C14.1 C15.2 C16.1 C17.1 C19.1 C20.2 C21.2 C24.2 C25.1 C26.1 C27.1 C28.2 C32.1 C33.1 C34.1 C35.1 C39.2 C40.2(-) C43.2 C47.2 C245.1 C246.1 C247.1 C248.1 D2.2(A) L2.1 L3.1 R10.1 R15.2 R17.1 R30.1 R42.1 R237.1 R328.1 R329.1 R330.1 TP4.1 TP17.1 U2.18(SOURCE) U2.19(SOURCE) U2.20(SOURCE) U2.21(SOURCE) U2.22(SOURCE) U2.23(SOURCE) U2.24(SOURCE) U2.25(SOURCE) U2.26(SOURCE) U2.28(SOURCE) U2.29(SOURCE) U2.30(SOURCE) U2.31(SOURCE) U2.32(SOURCE) U2.33(SOURCE) U2.34(SOURCE) U2.35(SOURCE) U2.36(SOURCE) U2.37(SOURCE) U2.38(SOURCE) U2.39(SOURCE) U3.19(VEE) U3.20(VEE) U3.21(VEE) U3.22(VEE) U3.23(VEE) U3.24(VEE) U3.25(VEE) U3.26(VEE) U3.27(VEE) U3.30(VEE) U3.31(VEE) U3.35(VEEA) U3.36(VEE) U4.18(SOURCE) U4.19(SOURCE) U4.20(SOURCE) U4.21(SOURCE) U4.22(SOURCE) U4.23(SOURCE) U4.24(SOURCE) U4.25(SOURCE) U4.26(SOURCE) U4.28(SOURCE) U4.29(SOURCE) U4.30(SOURCE) U4.31(SOURCE) U4.32(SOURCE) U4.33(SOURCE) U4.34(SOURCE) U4.35(SOURCE) U4.36(SOURCE) U4.37(SOURCE) U4.38(SOURCE) U4.39(SOURCE) U5.8(GND1) U6.3(GND) U7.3(GND) U8.2(DRAIN) U8.3(DRAIN) U8.4(DRAIN) U8.5(DRAIN) U8.6(DRAIN) U8.7(DRAIN) U8.8(DRAIN) U8.9(DRAIN) U8.10(DRAIN) U8.11(DRAIN) U8.12(DRAIN) U8.13(DRAIN) U8.14(DRAIN) U8.15(DRAIN) ; port SW_1
DC Bus+: C30.1 C31.1 C46.1 U2.2(DRAIN) U2.3(DRAIN) U2.4(DRAIN) U2.5(DRAIN) U2.6(DRAIN) U2.7(DRAIN) U2.8(DRAIN) U2.9(DRAIN) U2.10(DRAIN) U2.11(DRAIN) U2.12(DRAIN) U2.13(DRAIN) U2.14(DRAIN) U2.15(DRAIN) ; port DC Bus+
~{FAULT}_~{OC}_S1: C37.2 R31.1 ; port ~{FAULT}_~{OC}_S1
~{FAULT}_~{OC}_S1_init: R32.2 U6.4(Y)
~{FAULT}_~{OC}_S2_init: U25.4(Y) ; port ~{FAULT}_~{OC}_S2_init
~{FAULT}_~{OC}_S5: C36.2 R28.1 ; port ~{FAULT}_~{OC}_S5
~{FAULT}_~{OC}_S5_init: R29.2 U7.4(Y)
~{FAULT}_S1: C245.2 R237.2 U2.46(~{FAULT}) U6.1(A)
~{FAULT}_S2_init: C253.2 R335.2 U8.46(~{FAULT}) U25.1(A)
~{FAULT}_S5: C247.2 R329.2 U4.46(~{FAULT}) U7.1(A)
IN_PWM_S1: C13.2 R9.2 U2.45(IN)
IN_PWM_S5: C26.2 R8.2 U4.45(IN)
~{OC}_S1: C246.2 R328.2 U2.48(~{OC}) U6.2(B)
~{OC}_S2_init: C255.2 R337.2 U8.48(~{OC}) U25.2(B)
~{OC}_S5: C248.2 R330.2 U4.48(~{OC}) U7.2(B)
PWM_S1_Buff: R22.1 ; port PWM_S1_Buff
PWM_S2_Buff: R35.1 ; port PWM_S2_Buff
PWM_S5_Buff: R20.1 ; port PWM_S5_Buff
SW_mid: TP1.1 TP5.1 U4.2(DRAIN) U4.3(DRAIN) U4.4(DRAIN) U4.5(DRAIN) U4.6(DRAIN) U4.7(DRAIN) U4.8(DRAIN) U4.9(DRAIN) U4.10(DRAIN) U4.11(DRAIN) U4.12(DRAIN) U4.13(DRAIN) U4.14(DRAIN) U4.15(DRAIN) ; port SW_mid
TEMP_S1: R26.1 ; port TEMP_S1
TEMP_S1_init: R27.2 U2.49(TEMP)
TEMP_S2_init: C52.2 R37.1 ; port TEMP_S2_init
TEMP_S5: R24.1 ; port TEMP_S5
TEMP_S5_init: R25.2 U4.49(TEMP)
NetC14_2: C14.2 R10.2 U2.50(RDRV)
NetC15_1: C15.1 D4.1(CATHODE) U2.40(VNEG) U2.41(VNEG)
NetC18_2: C18.2 C22.1 FB2.2 U3.6(VIN) U3.7(VIN)
NetC21_1: C21.1 R12.2 R15.1 U3.33(FBVEE) U3.34(FBVDD)
NetC23_2: C23.2 R13.2 R14.2 U3.4(ENA)
NetC25_2: C25.2 U4.51(LDO5V)
NetC27_2: C27.2 R30.2 U4.50(RDRV)
NetC28_1: C28.1 D10.1(CATHODE) U4.40(VNEG) U4.41(VNEG)
NetC32_2: C32.2 R32.1 U5.2(INA)
NetC33_2: C33.2 R29.1 U5.3(INB)
NetC34_2: C34.2 R27.1 U5.4(INC)
NetC35_2: C35.2 R25.1 U5.5(IND)
NetC38_1: C38.1 FB3.2 U5.16(VCC2)
NetC41_2: C41.2 R22.2 U5.11(INE)
NetC42_2: C42.2 R20.2 U5.10(INF)
NetC50_2: C50.2 U8.51(LDO5V)
NetC51_2: C51.2 R35.2 U8.45(IN)
NetC53_2: C53.2 R40.2 U8.50(RDRV)
NetC54_1: C54.1 D25.1(CATHODE) U8.40(VNEG) U8.41(VNEG)
NetD1_2: D1.2(ANODE) R7.2 R41.2
NetD4_2: D4.2(ANODE) R17.2
NetD10_2: D10.2(ANODE) R42.2
NetD25_2: D25.2(ANODE) R43.2
NetL2_2: L2.2 U2.42(BBSW)
NetL3_2: L3.2 U4.42(BBSW)
NetL5_2: L5.2 U8.42(BBSW)
NetR8_1: R8.1 U5.7(OUTF)
NetR9_1: R9.1 U5.6(OUTE)
NetR11_2: R11.2 U3.3(~{PG})
NetR24_2: R24.2 U5.12(OUTD)
NetR26_2: R26.2 U5.13(OUTC)
NetR28_2: R28.2 U5.14(OUTB)
NetR31_2: R31.2 U5.15(OUTA)
NetR37_2: R37.2 U8.49(TEMP)

Not connected (* = marked no-connect by the designer): U2 1(1_NU)* 16(1_NU)* 17(2_NU)* 27(2_NU)* 43(2_NU)* 47(2_NU)* 52(2_NU)*; U3 32(RLIM)*; U4 1(1_NU)* 16(1_NU)* 17(2_NU)* 27(2_NU)* 43(2_NU)* 47(2_NU)* 52(2_NU)*; U8 1(1_NU)* 16(1_NU)* 17(2_NU)* 27(2_NU)* 43(2_NU)* 47(2_NU)* 52(2_NU)*

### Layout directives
net class HV_SW_Node1: 5V_SW1, 12V_HVN, 12V_SW1, GND_HVN, IN_PWM_S1, IN_PWM_S5, SW_1, TEMP_S1_init, TEMP_S5_init, ~{FAULT}_S1, ~{FAULT}_S5, ~{FAULT}_~{OC}_S1_init, ~{FAULT}_~{OC}_S5_init, ~{OC}_S1, ~{OC}_S5
net class HVN: 3V3_HVN, 12V_HVN, DC Bus-, GND_HVN, ~{FAULT}_S2_init, ~{OC}_S2_init
net class HVP: DC Bus+
net class HV_SW_Mid: SW_mid

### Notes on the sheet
- 20+ 10+ 1.2mA = 31.2mA @ 12V
- (near C40) 20mA @ 12V
- Vin= 10-18V (12V nom)
  12V Vin/12V Vout
  1.5-W output at TA= 105 °C
  VEnable= 0-5.5V
  Trigger at 10.5V
  Enable threshold 2.1V
- 1.2mA @ 12V
- 10mA @ 5V
- (near C42) R= 56Ohm, C= 220pF
  𝜏= 1.23e-8
  fc= 12.918MHz
- Vin= 2.25 to 5.5V
  100 Mbps
  1.4mA/channel at 1Mbps
  Prop. delay= 16ns
  Basic Insulation
- Referenced at DC Bus-

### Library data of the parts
C11 C24 C49 = CMP-0750154-1: CAP, CERM, 10 µF, 25 V,+/- 10%, X7R, AEC-Q200 Grade 1, 1206; Manufacturer: Taiyo Yuden; AEC Qualified: Y; SizeZ_mm: 1.8; TaMax_C: 125°C; TaMin_C: -55°C; Cap_Case: 1206; Polarized: N; AEC Grade: 1; SizeY_mm: 1.6; Value: 10uF; SizeX_mm: 3.2; SizeAreaWB_mm2: 10.92; AEC Category: Q200; U/M: EA; SizeArea_mm2: 5.12
C12 = CMP-0007389-4: CAP, CERM, 0.22 uF, 16 V, +/- 10%, X7R, 0603; Manufacturer: MuRata; TaMin_C: -55°C; Polarized: N; SizeAreaWB_mm2: 4.68; Value1: Unknown; U/M: EA; Value: 0.22uF; TaMax_C: 125°C; SizeZ_mm: 1; SizeX_mm: 1.6; SizeY_mm: 0.8; SizeArea_mm2: 1.28; AEC Category: Q200
C13 C14 C26 C27 C32-C37 C41 C42 C51-C53 C245-C248 C253 C255 = CMP-0007442-5: as C9 on sheet TIDA-010938 AC-DC_Cover Sheet
C15 C28 C54 = CMP-0007975-2: CAP, CERM, 2.2 uF, 25 V, +/- 10%, X7R, AEC-Q200 Grade 1, 0805; Manufacturer: TDK; TaMin_C: -55°C; Polarized: N; SizeAreaWB_mm2: 6.75; Value1: Unknown; U/M: EA; Value: 2.2uF; TaMax_C: 125°C; SizeZ_mm: 1.45; SizeX_mm: 2; SizeY_mm: 1.25; Cap_Case: 0805; SizeArea_mm2: 2.5; AEC Qualified: Y; AEC Grade: 1; AEC Category: Q200
C16 C25 C43 C47 C50 C185 = CMP-0006752-5: as C6 on sheet TIDA-010938 AC-DC_Cover Sheet
C17 = CMP-0086152-1: as C7 on sheet TIDA-010938 AC-DC_Cover Sheet
C18 = CMP-0009474-2: CAP, CERM, 20 uF, 16 V, +/- 20%, X5R, 0704; Manufacturer: MuRata; TaMin_C: -55°C; Polarized: N; SizeAreaWB_mm2: 5.6; Value1: Unknown; U/M: EA; Value: 20uF; TaMax_C: 85°C; SizeZ_mm: 0.8; SizeX_mm: 1; SizeY_mm: 1.8; Cap_F: 20µF; AEC Category: Q200
C19 = CMP-0007507-5: CAP, CERM, 10 uF, 25 V, +/- 20%, X5R, 0603; Manufacturer: Taiyo Yuden; TaMin_C: -55°C; Polarized: N; SizeAreaWB_mm2: 4.68; Value1: Unknown; U/M: EA; TaMax_C: 85°C; SizeZ_mm: 1; SizeX_mm: 1.6; SizeY_mm: 0.8; SizeArea_mm2: 1.28; Cap_F: 10µF; AEC Category: Q200
C20 = CMP-0094458-1: 10µF ±20% 25V Ceramic Capacitor X5R 0603 (1608 Metric); Manufacturer: Murata Electronics; SizeZ_mm: 1.2mm; AEC Qualified: No
C21 = CMP-0007209-4: CAP, CERM, 330 pF, 50 V, +/- 5%, C0G/NP0, 0603; Manufacturer: MuRata; TaMin_C: -55°C; Polarized: N; SizeAreaWB_mm2: 4.68; Value1: Unknown; U/M: EA; Value: 330pF; TaMax_C: 125°C; SizeZ_mm: 1; SizeX_mm: 1.6; SizeY_mm: 0.8; SizeArea_mm2: 1.28; AEC Category: Q200
C22 C38 C39 = CMP-0006837-4: CAP, CERM, 0.1 uF, 50 V, +/- 10%, X7R, 0603; Manufacturer: Wurth Elektronik; TaMin_C: -55°C; Polarized: N; SizeAreaWB_mm2: 4.68; Value1: Unknown; U/M: EA; Value: 0.1uF; TaMax_C: 125°C; SizeZ_mm: 1; SizeX_mm: 1.6; SizeY_mm: 0.8; Value2: 50V; SizeArea_mm2: 1.28; CompType: Capacitor; Cap_F: 100nF; AEC Category: Q200
C23 = CMP-0750039-1: as C8 on sheet TIDA-010938 AC-DC_Cover Sheet
C30 C31 C46 = CMP-0009326-2: CAP, CERM, 0.1 uF, 1000 V, +/- 10%, X7R, 1812; Manufacturer: Kemet; Polarized: N; Value: 0.1uF; U/M: EA; Cap_F: 100nF; Value1: Unknown; VDC_V: 1kV; Value2: 1000V; TaMin_C: -55°C; TaMax_C: 125°C; Cap_Case: 1812; AEC Category: Q200; SizeArea_mm2: 14.4; SizeAreaWB_mm2: 23.1; SizeX_mm: 4.5; SizeY_mm: 3.2; SizeZ_mm: 2.54
C40 C238 C239 = CMP-0081462-1: CAP, AL, 100 µF, 25 V, +/- 20%, SMD; Manufacturer: Nichicon; TaMin_C: -55°C; Polarized: Y; SizeAreaWB_mm2: 77.4; U/M: EA; Value: 100uF; TaMax_C: 105°C; SizeZ_mm: 8; SizeX_mm: 7; SizeY_mm: 6.6; Cap_Case: 6.3x7.7mm; SizeArea_mm2: 46.2; CompType: Capacitor; AEC Qualified: N; IRMS_A: 91mA; AEC Category: Q200
D1 = CMP-0095009-1: Diode Silicon Carbide Schottky 1200 V 2A (DC) Surface Mount DO-214AA; Manufacturer: GeneSiC Semiconductor; Max Surge Forward Current: 20A; ValueDisplayed: 122pF; Vf_V: 1.2kV; Peak Reverse Current: 1uA; SizeZ_mm: 2.44mm; AEC Qualified: No; TJmax_C: 175°C
D2 = CMP-0005769-4: Diode, Zener, 16 V, 500 mW, AEC-Q101, SOD-123; Manufacturer: Diodes Inc.; SizeZ_mm: 1.35; AEC Qualified: Y; SizeX_mm: 3.85; AEC Category: Q101; Power_W: 500mW; SizeY_mm: 1.7; Value1: 0.5W; SizeAreaWB_mm2: 13.095; SizeArea_mm2: 6.545; RJA_CperW: 338
D4 D10 D25 = CMP-0093310-1: Standard LEDs - SMD Green TOPLED E 1608; Manufacturer: Osram Opto; AEC Grade: Grade 2; LambdaP: 572nm; SizeZ_mm: 0.7mm; LuminousFlux_PhiV: 0.016-0.0295lm; Luminous Intensity: 4.5-9.7mcd; LambdaD: 570nm; Tjmax_C: 125°C; Angle: 120°; Led Orientation: Top View; Forward Current: 2mA; Vf_V: 1.8V; AEC Qualified: Yes; Vr_V: 12V
FB2 FB3 = CMP-0037505-1: as FB1 on sheet TIDA-010938 AC-DC_Cover Sheet
L2 L3 L5 = CMP-0089347-1: 4.7µH Unshielded Inductor 1.1A 426mOhm Max 0806 (2016 Metric); Manufacturer: Cyntec; AEC Qualified: No; Material: Metal Dust; Isat: 1.26A; Test Frequency: 1MHz; DCR_ohm: 0.426; SizeZ_mm: 1mm; Tolerance_%: 20%
R7 R41 = CMP-0018694-3: RES, 4.7, 5%, 0.75 W, AEC-Q200 Grade 0, 1206; Manufacturer: Vishay-Dale; Power_W: 750mW; TempCo: 200 ppm/C; Value_Code: 4R70; Value: 4.7; EIA_Code: E24; SizeX_mm: 3.2; SizeY_mm: 1.6; SizeZ_mm: 1.35; Value2: 0.75W; SizeArea_mm2: 5.12; AEC Qualified: Y; AEC Grade: 0; AEC Category: Q200
R8 R9 R20 R22 R24-R29 R31 R32 R35 R37 = CMP-0023572-3: as R2 on sheet TIDA-010938 AC-DC_Cover Sheet
R10 R30 R40 = CMP-0022906-5: RES, 20.0 k, 1%, 0.1 W, 0603; Manufacturer: Yageo; Power_W: 100mW; TempCo: 100 ppm/C; Value_Code: 20k0; Value: 20.0k; EIA_Code: E96; Res_ohm: 20k; SizeX_mm: 1.6; SizeY_mm: 0.8; SizeZ_mm: 1; Value2: 0.1W; SizeArea_mm2: 1.28; AEC Qualified: N; VDC_V: 75V; AEC Category: Q200; SizeAreaWB_mm2: 4.68
R11 R13 = CMP-0022685-3: RES, 12.0 k, 1%, 0.1 W, 0603; Manufacturer: Panasonic; Power_W: 100mW; TempCo: 100 ppm/C; Value_Code: 12k0; U/M: EA; Value: 12.0k; Res_ohm: 12k; SizeX_mm: 1.6; SizeY_mm: 0.8; SizeZ_mm: 1; Value2: 0.1W; SizeArea_mm2: 1.28; VDC_V: 75V; AEC Category: Q200
R12 = CMP-0025200-2: RES, 38.8 k, 0.5%, 0.1 W, 0603; Manufacturer: Yageo America; Power_W: 100mW; TempCo: 50 ppm/C; Value_Code: 38k8; U/M: EA; Value: 38.8k; EIA_Code: E192; SizeX_mm: 1.6; SizeY_mm: 0.8; SizeZ_mm: 1; Value2: 0.1W; SizeArea_mm2: 1.28; VDC_V: 75V; AEC Category: Q200
R14 = CMP-0023076-5: RES, 3.01 k, 1%, 0.1 W, 0603; Manufacturer: Yageo; Power_W: 100mW; TempCo: 100 ppm/C; Value_Code: 3k01; Value: 3.01k; EIA_Code: E96; SizeX_mm: 1.6; SizeY_mm: 0.8; SizeZ_mm: 1; Value2: 0.1W; SizeArea_mm2: 1.28; AEC Qualified: N; VDC_V: 75V; AEC Category: Q200; SizeAreaWB_mm2: 4.68
R15 = CMP-0023404-1: RES, 10.0 k, 0.1%, 0.1 W, 0603; Manufacturer: Susumu Co Ltd; Power_W: 100mW; TempCo: 25 ppm/C; Value_Code: 10k0; U/M: EA; Value: 10.0k; EIA_Code: E192; Res_ohm: 10k; SizeX_mm: 1.6; SizeY_mm: 0.8; SizeZ_mm: 1; Value2: 0.1W; SizeArea_mm2: 1.28; VDC_V: 75V; AEC Category: Q200
R17 R42 R43 = CMP-0025933-5: RES, 5.6 k, 5%, 0.1 W, 0603; Manufacturer: Yageo; Power_W: 100mW; TempCo: 100 ppm/C; Value_Code: 5k60; Value: 5.6k; EIA_Code: E24; SizeX_mm: 1.6; SizeY_mm: 0.8; SizeZ_mm: 1; Value2: 0.1W; SizeArea_mm2: 1.28; AEC Qualified: N; VDC_V: 75V; AEC Category: Q200; SizeAreaWB_mm2: 4.68
R237 R328-R330 R335 R337 = CMP-0023404-3: as R5 on sheet TIDA-010938 AC-DC_Cover Sheet
TP1 TP5 TP11 TP16 TP17 = CMP-0003968-1: Test Point, SMT; Manufacturer: Harwin
TP2-TP4 TP6 = CMP-0055138-2: Test Point, Miniature, Black, TH; Manufacturer: Keystone Electronics; ContactFinish: Silver; CNHeader: FALSE; Green_Lifecycle: Active; Green_REACh: Passed; CT: TRUE
U2 U4 U8 = CMP-0094891-1: 650-V 30-mΩ GaN FET with Integrated Driver, Protection, and Temperature Reporting; Manufacturer: Texas Instruments; Max Supply Voltage: 18V; TaMax_C: +125°C; TaMin_C: -40°C; Nominal Supply Current: 16mA; Number Of Outputs: 1; Standoff Height: 0mm; Min Supply Voltage: 7.5V; TJmax_C: +150°C; AEC Grade: Grade 1; SizeZ_mm: 1mm; Output Voltage: 520V; AEC Qualified: Yes
U3 = CMP-0033793-2: Automotive 1.5-W, 12-V VIN / 12-VOUT, 15-V VIN / 15-V VOUT, HighDensity, > 5-kVRMS, Isolated DC/DC Module; Manufacturer: Texas Instruments; SizeZ_mm: 3.55mm; AEC Qualified: Yes; AEC Grade: Grade 1; Max Supply Voltage: 18V; Min Supply Voltage: 9V; Nominal Supply Current: 200-270mA; Number Of Outputs: 2; Output Type: AdjustableProgrammable; Output Voltage: 10-18V; Standoff Height: 0.1mm; Switching Frequency: 18MHz; TaMax_C: +125°C; TaMin_C: -40°C; TJmax_C: +150°C; AEC Category: Q200; CompType: IC
U5 = CMP-0067607-3: High Speed, Robust EMC, Reinforced Six-Channel Digital Isolator, DBQ0016A (SSOP-16); Manufacturer: Texas Instruments; SizeX_mm: 6.0; SizeY_mm: 10.0; CompType: IC; SizeZ_mm: 1.75; SizeArea_mm2: 60.0; SizeAreaWB_mm2: 96.0; U/M: EA; AEC Category: Q200; AEC Qualified: N
U6 U7 U25 = CMP-0051571-2: Single 2-Input Positive-AND Gate, DBV0005A, SMALL T&R; Manufacturer: Texas Instruments; Voltage(Nom)(V): 1.8,2.5,3.3,5; Bits(#): 1; Rating: Catalog; F @ Nom Voltage(Max)(Mhz): 150; 3-State Output: No; Gate Type: AND; Output Drive (IOL/IOH)(Max)(mA): 32/-32; Technology Family: LVC; Logic: True; VCC(Max)(V): 5.5; ICC @ Nom Voltage(Max)(mA): 0.01; VCC(Min)(V): 1.65; tpd @ Nom Voltage(Max)(ns): 4.5,6,4,5; Input Type: CMOS/TTL; Output Type: CMOS; AEC Category: Q200; AEC Qualified: N; CompType: IC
